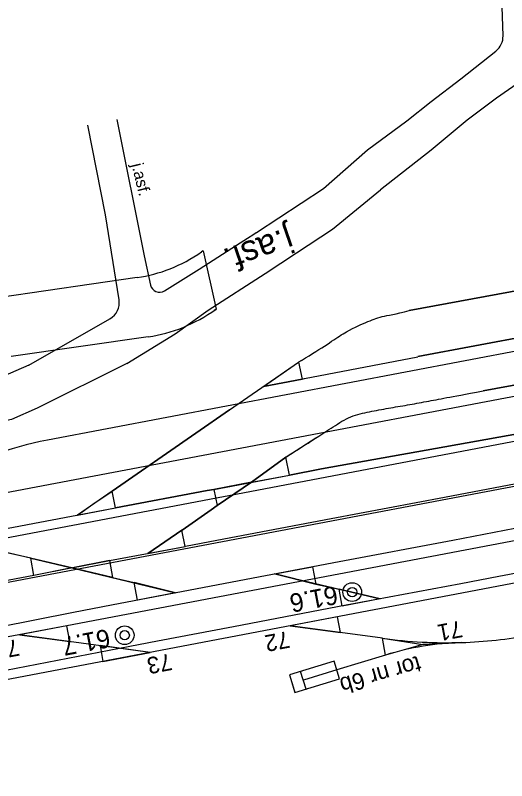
# Model space of a CAD drawing. Extents: x 6541740 to 6566395, y 5525066 to 5530361.
# Drawn here: x 6557139.8 to 6557192.8, y 5526138.9 to 5526221.5 of the extents above; entities that cross this region are included whole.
import ezdxf

# ---------------------------------------------------------------- set-up
doc = ezdxf.new("R2010")
doc.units = 0
for name, color, linetype in [('Domyślna', 7, 'Continuous'), ('ps_wymiarowanie', 7, 'Continuous'), ('TOR_PRZEK_P-komponent', 7, 'Continuous'), ('TOR_PRZEK_P-teren istniejacy', 7, 'Continuous'), ('TOR_PS_ODW-drenokolektory', 7, 'Continuous'), ('TOR_PS_ODW-odwodnienie liniowe', 7, 'Continuous'), ('TOR_PS_OPIS_O-opisy odwodnienia', 7, 'Continuous'), ('TOR_PS_OPIS_T-symbole geometrii', 7, 'Continuous'), ('TOR_PS_T-rowy otwarte nieumocnione', 7, 'Continuous'), ('TOR_PS_T-wypelnienia', 7, 'Continuous'), ('TOR_RAMKI-ramka+tabelka 1', 7, 'Continuous')]:
    doc.layers.add(name, color=color, linetype=linetype)

# ---------------------------------------------------------------- blocks, each defined once
blk = doc.blocks.new('koziol 15+5')
at = {"layer": 'Domyślna'}
for p, q in [((15, 1), (14.3, 1)), ((15, 1), (15, -1)), ((20, 0), (20, 1)), ((0, 0), (15, 0)), ((15, -1), (14.3, -1))]:
    blk.add_line(p, q, dxfattribs=at)
blk.add_lwpolyline([(20, 1), (0, 1), (0, -1), (20, -1)], close=True, dxfattribs=at)
blk = doc.blocks.new('4010_1')
at = {"layer": 'Domyślna'}
for radius in [0.75, 0.375]:
    blk.add_circle((0, 0), radius, dxfattribs=at)

msp = doc.modelspace()

# ---------------------------------------------------------------- linework, layer by layer
at = {"layer": 'Domyślna'}
msp.add_line((6557161.429, 5526189.759), (6557161.235, 5526189.628), dxfattribs=at)
msp.add_line((6557161.429, 5526189.759), (6557161.235, 5526189.628), dxfattribs=at)
at = {"layer": 'ps_wymiarowanie'}
msp.add_arc((6557155.337, 5526192.595), 1, 192.32011, 301.96364, dxfattribs=at)
msp.add_arc((6557155.337, 5526192.595), 1, 192.32011, 301.96364, dxfattribs=at)
at = {"layer": 'TOR_PRZEK_P-komponent'}
for p, q in [((6557416.454, 5526207.025), (6557145.327, 5526155.632)), ((6557211.116, 5526188.51), (6557143.226, 5526175.641)), ((6557212.028, 5526183.848), (6557116.502, 5526165.741)), ((6557019.224, 5526142.467), (6557215.881, 5526179.744)), ((6557102.514, 5526153.42), (6557216.785, 5526175.081)), ((6557216.049, 5526164.458), (6556955.024, 5526114.98)), ((6557174.558, 5526156.593), (6557169.449, 5526155.625)), ((6557145.327, 5526155.632), (6557123.539, 5526151.502)), ((6557145.327, 5526155.632), (6557140.218, 5526154.664)), ((6557179.398, 5526154.279), (6557169.449, 5526155.625)), ((6557154.32, 5526152.757), (6557140.218, 5526154.664)), ((6557149.212, 5526151.789), (6557154.32, 5526152.757)), ((6557179.726, 5526152.471), (6557174.461, 5526150.859))]:
    msp.add_line(p, q, dxfattribs=at)
for points in [[(6557169.449, 5526155.625), (6557174.862, 5526154.893), (6557174.558, 5526156.593)], [(6557140.218, 5526154.664), (6557145.631, 5526153.932), (6557145.327, 5526155.632)], [(6557154.32, 5526152.757), (6557148.908, 5526153.489), (6557149.212, 5526151.789)]]:
    msp.add_lwpolyline(points, dxfattribs=at)
msp.add_lwpolyline([(6557179.401, 5526154.279), (6557183.74, 5526153.602), (6557187.923, 5526153.824), (6557183.74, 5526153.602), (6557179.728, 5526152.472)], close=True, dxfattribs=at)
for centre, major_axis, start_param, end_param in [((6557254.968, 5525586.138), (-111.742, 589.503), 0, 0.083141), ((6557053.85, 5526901.342), (-141.54, 746.704), 3.058451, 3.102175), ((6557053.85, 5526901.342), (-141.54, 746.704), 3.102175, 3.141593), ((6557275.469, 5525665.722), (-92.42, 487.57), 6.243768, 6.31073), ((6557275.469, 5525665.722), (-92.42, 487.57), 6.243768, 6.31073)]:
    msp.add_ellipse(centre, major_axis=major_axis, ratio=0.25, start_param=start_param, end_param=end_param, dxfattribs=at)
at = {"layer": 'TOR_PS_ODW-drenokolektory'}
for points in [[(6557170.641, 5526184.256), (6557170.335, 5526184.046)], [(6557170.641, 5526184.256), (6557170.335, 5526184.046)], [(6557161.182, 5526170.338), (6557169.344, 5526171.886)], [(6557161.182, 5526170.338), (6557169.344, 5526171.886)]]:
    msp.add_lwpolyline(points, dxfattribs=at)
at = {"layer": 'TOR_PS_OPIS_T-symbole geometrii'}
for p, q in [((6557160.053, 5526196.076), (6557159.86, 5526195.945)), ((6557160.053, 5526196.076), (6557159.86, 5526195.945)), ((6557160.053, 5526196.076), (6557161.428, 5526189.761)), ((6557160.053, 5526196.076), (6557161.428, 5526189.761)), ((6557152.922, 5526193.181), (6557138.106, 5526191.044)), ((6557152.922, 5526193.181), (6557138.106, 5526191.044)), ((6557154.115, 5526186.792), (6557139.299, 5526184.655)), ((6557154.115, 5526186.792), (6557139.299, 5526184.655))]:
    msp.add_line(p, q, dxfattribs=at)
for major_axis, end_param in [((-45.954, 242.433), 3.249609), ((-45.954, 242.433), 3.249609), ((-47.164, 248.819), 3.253011), ((-47.164, 248.819), 3.253011)]:
    msp.add_ellipse((6557107.64, 5526435.726), major_axis=major_axis, ratio=0.25, start_param=3.130562, end_param=end_param, dxfattribs=at)
at = {"layer": 'TOR_PS_T-rowy otwarte nieumocnione'}
for p, q in [((6557182.296, 5526189.614), (6557194.571, 5526191.908)), ((6557194.571, 5526191.908), (6557182.296, 5526189.614)), ((6557182.296, 5526189.614), (6557194.571, 5526191.908)), ((6557194.571, 5526191.908), (6557182.296, 5526189.614)), ((6557162.896, 5526178.93), (6557170.335, 5526184.046)), ((6557162.896, 5526178.93), (6557170.335, 5526184.046)), ((6557162.896, 5526178.93), (6557170.335, 5526184.046)), ((6557162.896, 5526178.93), (6557170.335, 5526184.046)), ((6557166.556, 5526181.447), (6557170.734, 5526182.223)), ((6557166.556, 5526181.447), (6557170.734, 5526182.223)), ((6557166.556, 5526181.447), (6557170.734, 5526182.223)), ((6557166.556, 5526181.447), (6557170.734, 5526182.223)), ((6557190.271, 5526180.967), (6557196.408, 5526182.119)), ((6557196.408, 5526182.119), (6557190.271, 5526180.967)), ((6557190.271, 5526180.967), (6557196.408, 5526182.119)), ((6557196.408, 5526182.119), (6557190.271, 5526180.967)), ((6557160.485, 5526170.207), (6557150.574, 5526168.361)), ((6557150.574, 5526168.361), (6557160.485, 5526170.207)), ((6557160.485, 5526170.207), (6557150.574, 5526168.361)), ((6557150.574, 5526168.361), (6557160.485, 5526170.207)), ((6557142.417, 5526166.791), (6557150.574, 5526168.361)), ((6557142.417, 5526166.791), (6557150.574, 5526168.361)), ((6557142.417, 5526166.791), (6557150.574, 5526168.361)), ((6557142.417, 5526166.791), (6557150.574, 5526168.361)), ((6557154.072, 5526163.425), (6557157.754, 5526165.948)), ((6557154.072, 5526163.425), (6557157.754, 5526165.948)), ((6557154.072, 5526163.425), (6557157.754, 5526165.948)), ((6557154.072, 5526163.425), (6557157.754, 5526165.948)), ((6557149.921, 5526162.661), (6557158.091, 5526164.164)), ((6557149.921, 5526162.661), (6557158.091, 5526164.164)), ((6557141.436, 5526162.904), (6557150.24, 5526160.835)), ((6557141.436, 5526162.904), (6557150.24, 5526160.835)), ((6557149.921, 5526162.661), (6557141.766, 5526161.057)), ((6557149.921, 5526162.661), (6557141.766, 5526161.057)), ((6557149.921, 5526162.661), (6557141.766, 5526161.057)), ((6557149.921, 5526162.661), (6557141.766, 5526161.057)), ((6557145.865, 5526161.863), (6557157.043, 5526159.179)), ((6557145.865, 5526161.863), (6557157.043, 5526159.179)), ((6557150.24, 5526160.835), (6557152.594, 5526160.295)), ((6557150.24, 5526160.835), (6557152.594, 5526160.295)), ((6557167.77, 5526161.22), (6557172.21, 5526160.12)), ((6557167.77, 5526161.22), (6557172.21, 5526160.12)), ((6557157.043, 5526159.179), (6557152.594, 5526160.295)), ((6557157.043, 5526159.179), (6557152.594, 5526160.295)), ((6557179.136, 5526158.516), (6557174.722, 5526159.593)), ((6557179.136, 5526158.516), (6557174.722, 5526159.593))]:
    msp.add_line(p, q, dxfattribs=at)
for points in [[(6557183.226, 5526184.658), (6557195.505, 5526186.986), (6557207.841, 5526189.32), (6557220.011, 5526191.655), (6557232.366, 5526194.008), (6557244.641, 5526196.348)], [(6557244.641, 5526196.348), (6557232.366, 5526194.008), (6557220.011, 5526191.655), (6557207.841, 5526189.32), (6557195.505, 5526186.986), (6557183.226, 5526184.658)], [(6557183.226, 5526184.658), (6557195.505, 5526186.986), (6557207.841, 5526189.32), (6557220.011, 5526191.655), (6557232.366, 5526194.008), (6557244.641, 5526196.348)], [(6557244.641, 5526196.348), (6557232.366, 5526194.008), (6557220.011, 5526191.655), (6557207.841, 5526189.32), (6557195.505, 5526186.986), (6557183.226, 5526184.658)], [(6557170.734, 5526182.223), (6557170.991, 5526182.301), (6557183.227, 5526184.65)], [(6557170.734, 5526182.223), (6557170.991, 5526182.301), (6557183.227, 5526184.65)], [(6557170.734, 5526182.223), (6557170.991, 5526182.301), (6557183.227, 5526184.65)], [(6557170.734, 5526182.223), (6557170.991, 5526182.301), (6557183.227, 5526184.65)], [(6557170.641, 5526184.256), (6557170.335, 5526184.046)], [(6557170.641, 5526184.256), (6557170.335, 5526184.046)], [(6557268.852, 5526180.307), (6557260.657, 5526178.76), (6557260.657, 5526178.76), (6557248.388, 5526176.45), (6557248.388, 5526176.449), (6557236.094, 5526174.13), (6557236.094, 5526174.13), (6557223.819, 5526171.819), (6557223.819, 5526171.819), (6557211.543, 5526169.52), (6557211.543, 5526169.52), (6557203.346, 5526167.976), (6557199.25, 5526167.195), (6557199.249, 5526167.195), (6557186.987, 5526164.833), (6557186.987, 5526164.833), (6557174.708, 5526162.516), (6557162.421, 5526160.185), (6557162.421, 5526160.185), (6557150.132, 5526157.846), (6557150.132, 5526157.846), (6557146.037, 5526157.053), (6557137.851, 5526155.44)], [(6557268.852, 5526180.307), (6557260.657, 5526178.76), (6557260.657, 5526178.76), (6557248.388, 5526176.45), (6557248.388, 5526176.449), (6557236.094, 5526174.13), (6557236.094, 5526174.13), (6557223.819, 5526171.819), (6557223.819, 5526171.819), (6557211.543, 5526169.52), (6557211.543, 5526169.52), (6557203.346, 5526167.976), (6557199.25, 5526167.195), (6557199.249, 5526167.195), (6557186.987, 5526164.833), (6557186.987, 5526164.833), (6557174.708, 5526162.516), (6557162.421, 5526160.185), (6557162.421, 5526160.185), (6557150.132, 5526157.846), (6557150.132, 5526157.846), (6557146.037, 5526157.053), (6557137.851, 5526155.44)], [(6557150.199, 5526170.163), (6557159.251, 5526176.404), (6557162.896, 5526178.93)], [(6557162.896, 5526178.93), (6557159.251, 5526176.404), (6557150.199, 5526170.163)], [(6557150.199, 5526170.163), (6557159.251, 5526176.404), (6557162.896, 5526178.93)], [(6557162.896, 5526178.93), (6557159.251, 5526176.404), (6557150.199, 5526170.163)], [(6557197.409, 5526176.927), (6557185.105, 5526174.736), (6557172.832, 5526172.553), (6557169.344, 5526171.884)], [(6557169.344, 5526171.884), (6557172.832, 5526172.553), (6557185.105, 5526174.736), (6557197.409, 5526176.927)], [(6557197.409, 5526176.927), (6557185.105, 5526174.736), (6557172.832, 5526172.553), (6557169.344, 5526171.884)], [(6557169.344, 5526171.884), (6557172.832, 5526172.553), (6557185.105, 5526174.736), (6557197.409, 5526176.927)], [(6557168.952, 5526173.804), (6557172.209, 5526175.883)], [(6557168.952, 5526173.804), (6557172.209, 5526175.883)], [(6557165.264, 5526171.112), (6557168.952, 5526173.804)], [(6557168.952, 5526173.804), (6557165.264, 5526171.112)], [(6557165.264, 5526171.112), (6557168.952, 5526173.804)], [(6557168.952, 5526173.804), (6557165.264, 5526171.112)], [(6557198.358, 5526171.79), (6557186.11, 5526169.456), (6557173.848, 5526167.145), (6557161.527, 5526164.811), (6557158.117, 5526164.166), (6557158.091, 5526164.161)], [(6557198.358, 5526171.79), (6557186.11, 5526169.456), (6557173.848, 5526167.145), (6557161.527, 5526164.811), (6557158.117, 5526164.166), (6557158.091, 5526164.161)], [(6557161.182, 5526170.338), (6557169.344, 5526171.886)], [(6557161.182, 5526170.338), (6557169.344, 5526171.886)], [(6557161.54, 5526168.608), (6557165.264, 5526171.112)], [(6557165.264, 5526171.112), (6557161.54, 5526168.608)], [(6557161.54, 5526168.608), (6557165.264, 5526171.112)], [(6557165.264, 5526171.112), (6557161.54, 5526168.608)], [(6557146.476, 5526167.572), (6557148.145, 5526168.733), (6557150.199, 5526170.163)], [(6557146.476, 5526167.572), (6557148.145, 5526168.733), (6557150.199, 5526170.163)], [(6557146.476, 5526167.572), (6557148.145, 5526168.733), (6557150.199, 5526170.163)], [(6557146.476, 5526167.572), (6557148.145, 5526168.733), (6557150.199, 5526170.163)], [(6557161.182, 5526170.338), (6557160.485, 5526170.207)], [(6557160.485, 5526170.207), (6557161.182, 5526170.338)], [(6557161.182, 5526170.338), (6557160.485, 5526170.207)], [(6557160.485, 5526170.207), (6557161.182, 5526170.338)], [(6557157.754, 5526165.948), (6557157.758, 5526165.952), (6557160.91, 5526168.127)], [(6557160.91, 5526168.127), (6557157.758, 5526165.952), (6557157.754, 5526165.948)], [(6557157.754, 5526165.948), (6557157.758, 5526165.952), (6557160.91, 5526168.127)], [(6557160.91, 5526168.127), (6557157.758, 5526165.952), (6557157.754, 5526165.948)], [(6557160.91, 5526168.127), (6557161.54, 5526168.608)], [(6557161.54, 5526168.608), (6557160.91, 5526168.127)], [(6557160.91, 5526168.127), (6557161.54, 5526168.608)], [(6557161.54, 5526168.608), (6557160.91, 5526168.127)], [(6557136.703, 5526165.711), (6557142.417, 5526166.791)], [(6557136.703, 5526165.711), (6557142.417, 5526166.791)], [(6557145.865, 5526161.863), (6557132.578, 5526164.955)], [(6557145.865, 5526161.863), (6557132.578, 5526164.955)], [(6557141.436, 5526162.904), (6557137.046, 5526163.881)], [(6557141.436, 5526162.904), (6557137.046, 5526163.881)], [(6557200.161, 5526162.505), (6557191.968, 5526160.933), (6557187.871, 5526160.155), (6557187.871, 5526160.155), (6557175.493, 5526157.832), (6557163.298, 5526155.517), (6557163.298, 5526155.517), (6557155.096, 5526153.967), (6557150.996, 5526153.183), (6557150.996, 5526153.183), (6557138.722, 5526150.799)], [(6557200.161, 5526162.505), (6557191.968, 5526160.933), (6557187.871, 5526160.155), (6557187.871, 5526160.155), (6557175.493, 5526157.832), (6557163.298, 5526155.517), (6557163.298, 5526155.517), (6557155.096, 5526153.967), (6557150.996, 5526153.183), (6557150.996, 5526153.183), (6557138.722, 5526150.799)], [(6557141.766, 5526161.057), (6557136.974, 5526160.162), (6557133.597, 5526159.531)], [(6557141.766, 5526161.057), (6557136.974, 5526160.162), (6557133.597, 5526159.531)], [(6557167.77, 5526161.219), (6557179.136, 5526158.516)], [(6557167.77, 5526161.219), (6557179.136, 5526158.516)], [(6557172.21, 5526160.12), (6557174.722, 5526159.593)], [(6557172.21, 5526160.12), (6557174.722, 5526159.593)]]:
    msp.add_lwpolyline(points, dxfattribs=at)
for points in [[(6557166.556, 5526181.447), (6557170.335, 5526184.046), (6557170.734, 5526182.223)], [(6557166.556, 5526181.447), (6557170.335, 5526184.046), (6557170.734, 5526182.223)], [(6557165.264, 5526171.112), (6557169.344, 5526171.886), (6557168.952, 5526173.804)], [(6557165.264, 5526171.112), (6557169.344, 5526171.886), (6557168.952, 5526173.804)], [(6557165.264, 5526171.112), (6557161.182, 5526170.338), (6557161.54, 5526168.608)], [(6557165.264, 5526171.112), (6557161.182, 5526170.338), (6557161.54, 5526168.608)], [(6557146.476, 5526167.572), (6557150.574, 5526168.361), (6557150.199, 5526170.163)], [(6557146.476, 5526167.572), (6557150.574, 5526168.361), (6557150.199, 5526170.163)], [(6557154.072, 5526163.425), (6557158.091, 5526164.164), (6557157.754, 5526165.948)], [(6557154.072, 5526163.425), (6557158.091, 5526164.164), (6557157.754, 5526165.948)], [(6557145.865, 5526161.863), (6557141.766, 5526161.057), (6557141.436, 5526162.904)], [(6557145.865, 5526161.863), (6557141.766, 5526161.057), (6557141.436, 5526162.904)], [(6557145.865, 5526161.863), (6557149.921, 5526162.661), (6557150.24, 5526160.835)], [(6557145.865, 5526161.863), (6557149.921, 5526162.661), (6557150.24, 5526160.835)], [(6557167.77, 5526161.22), (6557171.856, 5526161.995), (6557172.21, 5526160.12)], [(6557167.77, 5526161.22), (6557171.856, 5526161.995), (6557172.21, 5526160.12)], [(6557157.043, 5526159.179), (6557152.951, 5526158.4), (6557152.594, 5526160.295)], [(6557157.043, 5526159.179), (6557152.951, 5526158.4), (6557152.594, 5526160.295)], [(6557179.136, 5526158.515), (6557175.044, 5526157.747), (6557174.722, 5526159.593)], [(6557179.136, 5526158.515), (6557175.044, 5526157.747), (6557174.722, 5526159.593)]]:
    msp.add_lwpolyline(points, close=True, dxfattribs=at)
for points in [[(6557170.641, 5526184.256), (6557173.012, 5526185.64), (6557175.309, 5526187.38), (6557177.752, 5526188.406), (6557179.223, 5526189.024), (6557180.782, 5526189.212), (6557182.296, 5526189.614)], [(6557170.641, 5526184.256), (6557173.012, 5526185.64), (6557175.309, 5526187.38), (6557177.752, 5526188.406), (6557179.223, 5526189.024), (6557180.782, 5526189.212), (6557182.296, 5526189.614)], [(6557170.641, 5526184.256), (6557173.012, 5526185.64), (6557175.309, 5526187.38), (6557177.752, 5526188.406), (6557179.223, 5526189.024), (6557180.782, 5526189.212), (6557182.296, 5526189.614)], [(6557170.641, 5526184.256), (6557173.012, 5526185.64), (6557175.309, 5526187.38), (6557177.752, 5526188.406), (6557179.223, 5526189.024), (6557180.782, 5526189.212), (6557182.296, 5526189.614)], [(6557168.952, 5526173.804), (6557170.038, 5526174.497), (6557171.124, 5526175.19), (6557172.209, 5526175.883), (6557174.086, 5526177.08), (6557175.963, 5526178.309), (6557178.002, 5526178.707), (6557180.041, 5526179.105), (6557182.093, 5526179.432), (6557184.134, 5526179.815), (6557186.18, 5526180.199), (6557188.225, 5526180.583), (6557190.271, 5526180.967)], [(6557168.952, 5526173.804), (6557170.038, 5526174.497), (6557171.124, 5526175.19), (6557172.209, 5526175.883), (6557174.086, 5526177.08), (6557175.963, 5526178.309), (6557178.002, 5526178.707), (6557180.041, 5526179.105), (6557182.093, 5526179.432), (6557184.134, 5526179.815), (6557186.18, 5526180.199), (6557188.225, 5526180.583), (6557190.271, 5526180.967)], [(6557168.952, 5526173.804), (6557170.038, 5526174.497), (6557171.124, 5526175.19), (6557172.209, 5526175.883), (6557174.086, 5526177.08), (6557175.963, 5526178.309), (6557178.002, 5526178.707), (6557180.041, 5526179.105), (6557182.093, 5526179.432), (6557184.134, 5526179.815), (6557186.18, 5526180.199), (6557188.225, 5526180.583), (6557190.271, 5526180.967)], [(6557168.952, 5526173.804), (6557170.038, 5526174.497), (6557171.124, 5526175.19), (6557172.209, 5526175.883), (6557174.086, 5526177.08), (6557175.963, 5526178.309), (6557178.002, 5526178.707), (6557180.041, 5526179.105), (6557182.093, 5526179.432), (6557184.134, 5526179.815), (6557186.18, 5526180.199), (6557188.225, 5526180.583), (6557190.271, 5526180.967)]]:
    msp.add_open_spline(points, degree=3, dxfattribs=at)
at = {"layer": 'TOR_PS_T-wypelnienia'}
for p, q in [((6557187.85, 5526214.628), (6557191.649, 5526217.614)), ((6557187.85, 5526214.628), (6557191.649, 5526217.614)), ((6557196.469, 5526215.865), (6557191.714, 5526212.544)), ((6557196.469, 5526215.865), (6557191.714, 5526212.544)), ((6557184.649, 5526212.189), (6557187.85, 5526214.628)), ((6557184.649, 5526212.189), (6557187.85, 5526214.628)), ((6557182.035, 5526210.101), (6557184.649, 5526212.189)), ((6557182.035, 5526210.101), (6557184.649, 5526212.189)), ((6557191.714, 5526212.544), (6557188.531, 5526210.177)), ((6557191.714, 5526212.544), (6557188.531, 5526210.177)), ((6557150.722, 5526210.224), (6557153.671, 5526195.537)), ((6557150.722, 5526210.224), (6557153.671, 5526195.537)), ((6557188.531, 5526210.177), (6557184.672, 5526206.942)), ((6557188.531, 5526210.177), (6557184.672, 5526206.942)), ((6557177.778, 5526206.955), (6557182.035, 5526210.101)), ((6557177.778, 5526206.955), (6557182.035, 5526210.101)), ((6557184.672, 5526206.942), (6557179.175, 5526202.656)), ((6557184.672, 5526206.942), (6557179.175, 5526202.656)), ((6557153.671, 5526195.537), (6557154.36, 5526192.382)), ((6557153.671, 5526195.537), (6557154.36, 5526192.382)), ((6557141.203, 5526183.72), (6557149.979, 5526188.748)), ((6557141.203, 5526183.72), (6557149.979, 5526188.748)), ((6557151.815, 5526183.908), (6557142.102, 5526179.089)), ((6557151.815, 5526183.908), (6557142.102, 5526179.089))]:
    msp.add_line(p, q, dxfattribs=at)
for points in [[(6557192.412, 5526219.256), (6557192.303, 5526222.391), (6557191.473, 5526226.122)], [(6557192.412, 5526219.256), (6557192.303, 5526222.391), (6557191.473, 5526226.122)], [(6557150.96, 5526190.796), (6557149.511, 5526199.953), (6557147.578, 5526209.63)], [(6557150.96, 5526190.796), (6557149.511, 5526199.953), (6557147.578, 5526209.63)], [(6557155.866, 5526191.747), (6557159.608, 5526194.081), (6557163.654, 5526196.677), (6557164.836, 5526197.435), (6557165.501, 5526197.861), (6557165.771, 5526198.034), (6557165.811, 5526198.06), (6557173.034, 5526202.796), (6557177.778, 5526206.955)], [(6557155.866, 5526191.747), (6557159.608, 5526194.081), (6557163.654, 5526196.677), (6557164.836, 5526197.435), (6557165.501, 5526197.861), (6557165.771, 5526198.034), (6557165.811, 5526198.06), (6557173.034, 5526202.796), (6557177.778, 5526206.955)], [(6557151.815, 5526183.908), (6557157.014, 5526187.131), (6557160.566, 5526189.681), (6557166.723, 5526193.63), (6557170.105, 5526195.847), (6557174.001, 5526198.401), (6557179.175, 5526202.656)], [(6557151.815, 5526183.908), (6557157.014, 5526187.131), (6557160.566, 5526189.681), (6557166.723, 5526193.63), (6557170.105, 5526195.847), (6557174.001, 5526198.401), (6557179.175, 5526202.656)], [(6557141.203, 5526183.72), (6557138.422, 5526182.496), (6557135.159, 5526181.784), (6557135.055, 5526181.774), (6557132.736, 5526181.545), (6557130.683, 5526181.342), (6557128.873, 5526181.291), (6557117.77, 5526180.299), (6557111.089, 5526179.527), (6557105.445, 5526178.877)], [(6557141.203, 5526183.72), (6557138.422, 5526182.496), (6557135.159, 5526181.784), (6557135.055, 5526181.774), (6557132.736, 5526181.545), (6557130.683, 5526181.342), (6557128.873, 5526181.291), (6557117.77, 5526180.299), (6557111.089, 5526179.527), (6557105.445, 5526178.877)], [(6557142.102, 5526179.089), (6557139.339, 5526177.865), (6557136.029, 5526177.143), (6557131.526, 5526176.699), (6557129.714, 5526176.647), (6557118.625, 5526175.656), (6557105.325, 5526174.12), (6557099.742, 5526173.501), (6557095.406, 5526173.19)], [(6557142.102, 5526179.089), (6557139.339, 5526177.865), (6557136.029, 5526177.143), (6557131.526, 5526176.699), (6557129.714, 5526176.647), (6557118.625, 5526175.656), (6557105.325, 5526174.12), (6557099.742, 5526173.501), (6557095.406, 5526173.19)]]:
    msp.add_lwpolyline(points, dxfattribs=at)
for centre, start, end in [((6557190.414, 5526219.186), 308.16037, 1.98836), ((6557190.414, 5526219.186), 308.16037, 1.98836), ((6557148.985, 5526190.483), 299.80833, 8.99392), ((6557148.985, 5526190.483), 299.80833, 8.99392)]:
    msp.add_arc(centre, 2, start, end, dxfattribs=at)

# ---------------------------------------------------------------- block references
at = {"layer": 'Domyślna', "xscale": 0.25141816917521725, "yscale": 0.9943593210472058, "rotation": -162.9778306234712}
msp.add_blockref('koziol 15+5', (6557174.461, 5526150.859), dxfattribs=at)
msp.add_blockref('koziol 15+5', (6557174.461, 5526150.859), dxfattribs=at)
at = {"layer": 'TOR_RAMKI-ramka+tabelka 1', "xscale": 1.345963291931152, "yscale": 1.345963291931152}
for p in [(6557176.13, 5526159.261), (6557151.568, 5526154.605)]:
    msp.add_blockref('4010_1', p, dxfattribs=at)

# ---------------------------------------------------------------- texts
at = {"layer": 'TOR_PRZEK_P-teren istniejacy'}
for height, rotation, p in [(1.2746, 283.68979, (6557152.295, 5526205.372)), (1.2746, 283.68979, (6557152.295, 5526205.372)), (2.7199, 199.06096, (6557169.245, 5526198.66)), (2.7199, 199.06096, (6557169.245, 5526198.66))]:
    msp.add_text('j.asf.', height=height, rotation=rotation, dxfattribs=at).set_placement(p)
at = {"layer": 'TOR_PS_ODW-odwodnienie liniowe'}
msp.add_text('tor nr 6b', height=1.8, rotation=196.09529, dxfattribs=at).set_placement((6557183.245, 5526152.423))
at = {"layer": 'TOR_PS_OPIS_O-opisy odwodnienia'}
for s, p in [('71', (6557187.844, 5526156.205)), ('72', (6557169.194, 5526155.065)), ('74', (6557140.008, 5526154.209)), ('73', (6557156.487, 5526152.656))]:
    msp.add_text(s, height=1.8, rotation=190.73324, dxfattribs=at).set_placement(p)
at = {"layer": 'TOR_RAMKI-ramka+tabelka 1'}
for s, p in [('61.6', (6557174.357, 5526159.969)), ('61.7', (6557149.791, 5526155.312))]:
    msp.add_text(s, height=2, rotation=190.76907, dxfattribs=at).set_placement(p)

doc.saveas('drawing.dxf')
